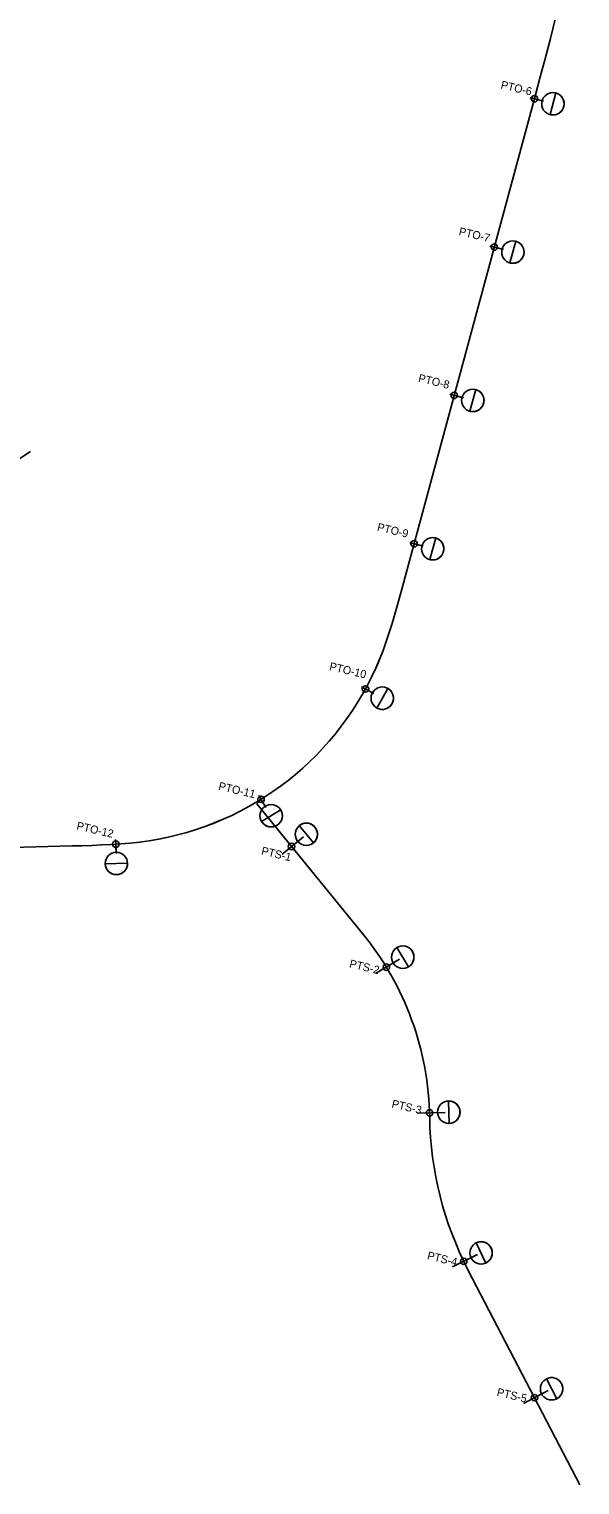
# Model space of a CAD drawing. Extents: x 0 to 511877, y 0 to 6211921.
# Drawn here: x 511654.3 to 511740.4, y 6211465.9 to 6211693.3 of the extents above; entities that cross this region are included whole.
import ezdxf

# ---------------------------------------------------------------- set-up
doc = ezdxf.new("R2010")
doc.units = 0
for name, color, linetype in [('Help', 7, 'Continuous'), ('TV_U_LYS_Ledn-', 7, 'Continuous'), ('TV_U_LYS_Ledn-ror', 7, 'Continuous'), ('TV_U_LYS_Mastenummer', 7, 'Continuous'), ('TV_U_LYS_Nyx330-Trafiksti', 7, 'Continuous')]:
    doc.layers.add(name, color=color, linetype=linetype)

msp = doc.modelspace()

# ---------------------------------------------------------------- linework, layer by layer
at = {"layer": 'Help'}
for p, q in [((511732.57, 6211682.59), (511734.69, 6211682)), ((511726.31, 6211659.42), (511728.42, 6211658.84)), ((511720.04, 6211636.25), (511722.16, 6211635.67)), ((511713.78, 6211613.08), (511715.89, 6211612.5)), ((511706.24, 6211590.55), (511708.15, 6211589.47)), ((511690.18, 6211573.56), (511691.31, 6211571.68)), ((511691.95, 6211569.7), (511706.4, 6211552.02)), ((511667.81, 6211566.67), (511667.96, 6211564.48)), ((511693.78, 6211564.36), (511697.17, 6211567.13)), ((511708.45, 6211545.75), (511712.2, 6211547.99)), ((511714.93, 6211523.95), (511719.3, 6211524.05)), ((511720.46, 6211499.94), (511724.38, 6211501.86)), ((511722.93, 6211499.38), (511740.36, 6211465.88)), ((511731.54, 6211478.6), (511735.41, 6211480.61))]:
    msp.add_line(p, q, dxfattribs=at)
for points in [[(511738.8, 6211706.79), (511738.33, 6211703.78), (511737.78, 6211700.79), (511737.16, 6211697.8), (511736.48, 6211694.82), (511735.75, 6211691.83), (511734.98, 6211688.83), (511734.18, 6211685.83), (511733.37, 6211682.82), (511712.7, 6211606.36), (511712.29, 6211604.86), (511711.88, 6211603.37), (511711.46, 6211601.9), (511711.03, 6211600.45), (511710.58, 6211599.01), (511710.11, 6211597.6), (511709.61, 6211596.22), (511709.06, 6211594.83)], [(511650.75, 6211618.38), (511650.39, 6211624.61), (511654.54, 6211627.27)], [(511673.05, 6211566.5), (511671.58, 6211566.29), (511670.11, 6211566.13), (511668.63, 6211566.01), (511667.13, 6211565.91), (511665.61, 6211565.83), (511664.09, 6211565.77), (511662.55, 6211565.72), (511660.99, 6211565.68), (511657.24, 6211565.58), (511653.47, 6211565.47), (511649.71, 6211565.35), (511645.93, 6211565.2), (511642.15, 6211565.03), (511638.37, 6211564.82), (511634.58, 6211564.56), (511630.79, 6211564.25), (511627, 6211563.88), (511623.2, 6211563.45), (511619.43, 6211562.94), (511619.42, 6211562.94)]]:
    msp.add_lwpolyline(points, dxfattribs=at)
for centre, radius, start, end in [((511666, 6211612.51), 46.55, 278.7078, 337.6769), ((511670.35, 6211522.56), 46.55, 0.8553, 39.2603), ((511770.34, 6211524.05), 53.45, 180.8553, 207.4882)]:
    msp.add_arc(centre, radius, start, end, dxfattribs=at)
at = {"layer": 'TV_U_LYS_Ledn-'}
for p, q in [((511690.55, 6211572.96), (511689.87, 6211572.25)), ((511693.04, 6211568.36), (511706.4, 6211552.02)), ((511722.93, 6211499.38), (511733.27, 6211479.5))]:
    msp.add_line(p, q, dxfattribs=at)
for points in [[(511738.8, 6211706.8), (511738.33, 6211703.78), (511737.78, 6211700.79), (511737.16, 6211697.8), (511736.48, 6211694.82), (511735.75, 6211691.83), (511734.98, 6211688.83), (511734.18, 6211685.83), (511733.37, 6211682.82), (511712.7, 6211606.36), (511712.29, 6211604.86), (511711.88, 6211603.37), (511711.46, 6211601.9), (511711.03, 6211600.45), (511710.58, 6211599.01), (511710.11, 6211597.6), (511709.61, 6211596.22), (511709.06, 6211594.83)], [(511673.05, 6211566.5), (511671.58, 6211566.29), (511670.11, 6211566.13), (511668.63, 6211566.01), (511667.13, 6211565.91), (511665.61, 6211565.83), (511664.09, 6211565.77), (511662.55, 6211565.72), (511660.99, 6211565.68), (511657.24, 6211565.58), (511653.47, 6211565.47), (511649.71, 6211565.35), (511645.93, 6211565.2), (511642.15, 6211565.03), (511638.37, 6211564.82), (511634.58, 6211564.56), (511630.79, 6211564.25), (511627, 6211563.88), (511623.2, 6211563.45), (511619.43, 6211562.94), (511619.42, 6211562.94)]]:
    msp.add_lwpolyline(points, dxfattribs=at)
for centre, radius, start, end in [((511666, 6211612.51), 46.55, 278.7036, 337.6812), ((511670.35, 6211522.56), 46.55, 0.8553, 39.2603), ((511770.34, 6211524.05), 53.45, 180.8553, 207.4882)]:
    msp.add_arc(centre, radius, start, end, dxfattribs=at)
at = {"layer": 'TV_U_LYS_Ledn-ror'}
msp.add_line((511689.87, 6211572.25), (511693.04, 6211568.36), dxfattribs=at)
at = {"layer": 'TV_U_LYS_Nyx330-Trafiksti'}
for p, q in [((511733.74, 6211682.27), (511734.46, 6211682.07)), ((511736.61, 6211683.3), (511735.7, 6211679.92)), ((511736.61, 6211683.3), (511736.61, 6211683.3)), ((511730.35, 6211660.14), (511729.44, 6211656.76)), ((511730.35, 6211660.14), (511730.35, 6211660.14)), ((511727.48, 6211659.1), (511728.2, 6211658.9)), ((511724.09, 6211636.97), (511723.17, 6211633.59)), ((511724.09, 6211636.97), (511724.09, 6211636.97)), ((511721.21, 6211635.93), (511721.94, 6211635.74)), ((511714.95, 6211612.76), (511715.67, 6211612.56)), ((511717.83, 6211613.79), (511716.9, 6211610.41)), ((511717.83, 6211613.79), (511717.83, 6211613.79)), ((511707.3, 6211589.96), (511707.96, 6211589.6)), ((511710.33, 6211590.29), (511708.65, 6211587.22)), ((511710.33, 6211590.29), (511710.33, 6211590.29)), ((511693.62, 6211571.32), (511690.64, 6211569.48)), ((511690.81, 6211572.53), (511691.21, 6211571.89)), ((511693.62, 6211571.32), (511693.62, 6211571.32)), ((511696.51, 6211568.86), (511698.73, 6211566.15)), ((511696.51, 6211568.86), (511696.51, 6211568.86)), ((511695.69, 6211565.92), (511696.27, 6211566.39)), ((511667.87, 6211565.45), (511667.89, 6211564.7)), ((511669.69, 6211563), (511666.19, 6211562.9)), ((511669.69, 6211563), (511669.69, 6211563)), ((511711.78, 6211549.81), (511713.6, 6211546.81)), ((511711.78, 6211549.81), (511711.78, 6211549.81)), ((511710.55, 6211547.01), (511711.2, 6211547.4)), ((511719.83, 6211525.84), (511719.94, 6211522.34)), ((511719.83, 6211525.84), (511719.83, 6211525.84)), ((511717.38, 6211524.01), (511718.13, 6211524.03)), ((511724.16, 6211503.69), (511725.68, 6211500.53)), ((511724.16, 6211503.69), (511724.16, 6211503.69)), ((511722.67, 6211501.02), (511723.34, 6211501.35)), ((511735.13, 6211482.44), (511736.75, 6211479.33)), ((511735.13, 6211482.44), (511735.13, 6211482.44)), ((511733.72, 6211479.73), (511734.38, 6211480.08))]:
    msp.add_line(p, q, dxfattribs=at)
for centre, radius in [((511733.26, 6211682.4), 0.5), ((511736.15, 6211681.61), 1.75), ((511726.99, 6211659.23), 0.5), ((511729.89, 6211658.45), 1.75), ((511723.63, 6211635.28), 1.75), ((511720.73, 6211636.06), 0.5), ((511714.46, 6211612.89), 0.5), ((511717.36, 6211612.1), 1.75), ((511706.86, 6211590.2), 0.5), ((511709.49, 6211588.76), 1.75), ((511690.55, 6211572.96), 0.5), ((511692.13, 6211570.4), 1.75), ((511697.62, 6211567.5), 1.75), ((511667.86, 6211565.96), 0.5), ((511667.94, 6211562.95), 1.75), ((511695.3, 6211565.6), 0.5), ((511712.69, 6211548.31), 1.75), ((511710.13, 6211546.75), 0.5), ((511719.88, 6211524.09), 1.75), ((511716.88, 6211524), 0.5), ((511724.92, 6211502.11), 1.75), ((511722.22, 6211500.8), 0.5), ((511735.94, 6211480.89), 1.75), ((511733.27, 6211479.5), 0.5)]:
    msp.add_circle(centre, radius, dxfattribs=at)
for centre, start, end in [((511736.15, 6211681.61), 254.8525, 74.7825), ((511729.89, 6211658.45), 254.922, 74.8521), ((511723.63, 6211635.28), 254.8847, 74.8147), ((511717.36, 6211612.1), 254.647, 74.577), ((511709.49, 6211588.76), 241.3721, 61.3021), ((511692.13, 6211570.4), 211.8142, 31.7442), ((511697.62, 6211567.5), 309.3122, 129.2422), ((511667.94, 6211562.95), 181.6579, 1.588), ((511712.69, 6211548.31), 301.3201, 121.2501), ((511719.88, 6211524.09), 271.7798, 91.7098), ((511724.92, 6211502.11), 295.8386, 115.7686), ((511735.94, 6211480.89), 297.5401, 117.4701)]:
    msp.add_arc(centre, 1.75, start, end, dxfattribs=at)

# ---------------------------------------------------------------- texts
at = {"layer": 'TV_U_LYS_Mastenummer'}
for s, p in [('PTO-6', (511727.91, 6211684.02)), ('PTO-7', (511721.36, 6211661.13)), ('PTO-8', (511715.03, 6211638.2)), ('PTO-9', (511708.6, 6211614.94)), ('PTO-10', (511701.13, 6211593.18)), ('PTO-11', (511683.81, 6211574.48)), ('PTO-12', (511661.64, 6211568.28)), ('PTS-1', (511690.5, 6211564.37)), ('PTS-2', (511704.26, 6211546.74)), ('PTS-3', (511710.87, 6211524.86)), ('PTS-4', (511716.42, 6211501.14)), ('PTS-5', (511727.3, 6211479.82))]:
    msp.add_text(s, height=1.25, rotation=346.664, dxfattribs=at).set_placement(p)

doc.saveas('drawing.dxf')
